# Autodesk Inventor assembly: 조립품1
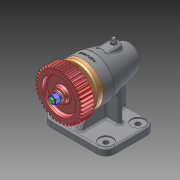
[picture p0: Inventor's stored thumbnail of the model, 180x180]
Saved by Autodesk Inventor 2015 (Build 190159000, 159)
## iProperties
Created: 2024-12
Part Number: 조립품1
Document SubType Name: Assembly
Designer: 102566
Author: 102566
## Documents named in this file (15)
- C:\Users\102566\Desktop\741204V1008\조립품1.iam
- C:\Users\102566\Desktop\741204V1008\본체.ipt
- C:\Users\102566\Desktop\741204V1008\앵귤러 볼 베어링 7003A.ipt
- C:\Users\102566\Desktop\741204V1008\앵귤러 볼 제어링 7204A.ipt
- C:\Users\102566\Desktop\741204V1008\오일 실 20 32 8.ipt
- C:\Users\102566\Desktop\741204V1008\축.ipt
- C:\Users\102566\Desktop\741204V1008\커버.ipt
- C:\Users\102566\Desktop\741204V1008\육각 소켓 머리 볼트 M4x10.ipt
- C:\Users\102566\Desktop\741204V1008\스퍼기어.ipt
- C:\Users\102566\Desktop\741204V1008\스프링 와셔 M8.ipt
- C:\Users\102566\Desktop\741204V1008\육각 너트 M8.ipt
- C:\Users\102566\Desktop\741204V1008\평와셔 M8.ipt
- C:\Users\102566\Desktop\741204V1008\평행 키 4x4x14.ipt
- C:\Users\102566\Desktop\741204V1008\그리스 니플 M6x0.75.ipt
- C:\Users\102566\Desktop\741204V1008\실링.ipt
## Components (1 placed, 1 different names)
1. 그리스 니플 M6x0.75:1
